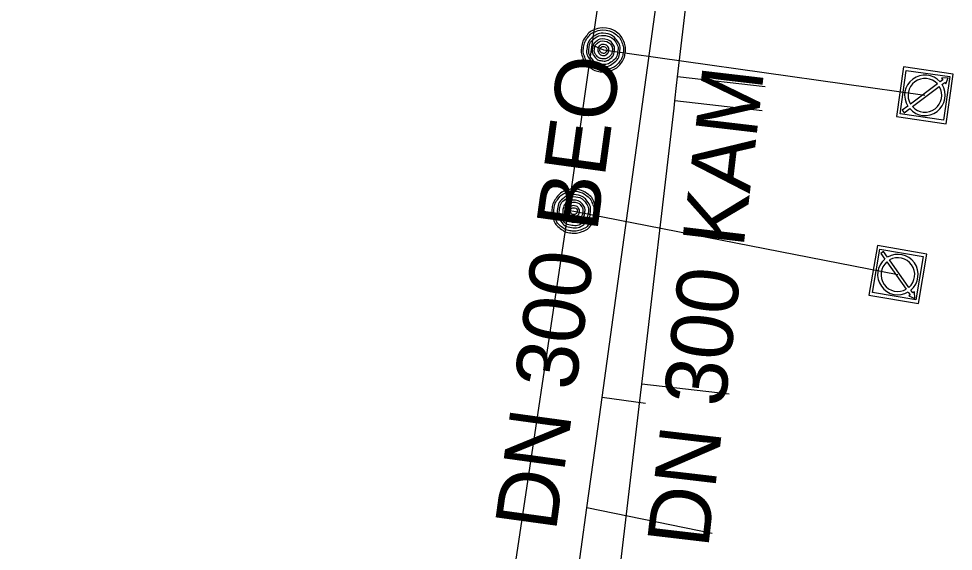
# Model space of a CAD drawing. Extents: x -595129 to -593591, y -1168385 to -1166898.
# Drawn here: x -594649.24 to -594628.01, y -1167201.97 to -1167189.88 of the extents above; entities that cross this region are included whole.
import ezdxf

# ---------------------------------------------------------------- set-up
doc = ezdxf.new("R2010")
doc.units = 0
for name, color, linetype in [('DA Kanalizační stoka popis', 7, 'Continuous'), ('Default', 7, 'Continuous'), ('Kanalizační přípojka', 7, 'Continuous'), ('Kanalizační stoka', 7, 'Continuous'), ('V Odběrné místo', 7, 'Continuous'), ('V Přípojka', 7, 'Continuous'), ('V Řad', 7, 'Continuous')]:
    doc.layers.add(name, color=color, linetype=linetype)

msp = doc.modelspace()

# ---------------------------------------------------------------- linework, layer by layer
at = {"layer": 'Default'}
for points in [[(-594635.888, -1167190.093), (-594635.764, -1167190.111), (-594635.654, -1167190.192), (-594635.545, -1167190.273), (-594635.495, -1167190.401), (-594635.445, -1167190.53), (-594635.464, -1167190.66), (-594635.482, -1167190.789), (-594635.564, -1167190.897), (-594635.646, -1167191.006), (-594635.774, -1167191.054), (-594635.901, -1167191.102), (-594636.03, -1167191.084), (-594636.159, -1167191.066), (-594636.267, -1167190.983), (-594636.376, -1167190.901), (-594636.424, -1167190.774), (-594636.473, -1167190.647), (-594636.454, -1167190.518), (-594636.436, -1167190.388), (-594636.352, -1167190.279), (-594636.269, -1167190.169), (-594636.141, -1167190.122), (-594636.014, -1167190.075), (-594635.888, -1167190.093)], [(-594635.895, -1167190.139), (-594636.008, -1167190.123), (-594636.124, -1167190.166), (-594636.24, -1167190.208), (-594636.315, -1167190.308), (-594636.391, -1167190.407), (-594636.408, -1167190.525), (-594636.425, -1167190.641), (-594636.381, -1167190.756), (-594636.337, -1167190.872), (-594636.238, -1167190.946), (-594636.14, -1167191.021), (-594636.024, -1167191.037), (-594635.907, -1167191.054), (-594635.791, -1167191.01), (-594635.675, -1167190.966), (-594635.601, -1167190.868), (-594635.527, -1167190.77), (-594635.51, -1167190.653), (-594635.493, -1167190.536), (-594635.539, -1167190.419), (-594635.584, -1167190.302), (-594635.683, -1167190.229), (-594635.782, -1167190.156), (-594635.895, -1167190.139)], [(-594635.907, -1167190.217), (-594635.75, -1167190.239), (-594635.658, -1167190.364), (-594635.565, -1167190.488), (-594635.587, -1167190.642), (-594635.609, -1167190.796), (-594635.734, -1167190.889), (-594635.858, -1167190.982), (-594636.013, -1167190.96), (-594636.166, -1167190.938), (-594636.259, -1167190.814), (-594636.353, -1167190.69), (-594636.331, -1167190.536), (-594636.308, -1167190.381), (-594636.185, -1167190.288), (-594636.062, -1167190.195), (-594635.907, -1167190.217)], [(-594635.913, -1167190.262), (-594636.049, -1167190.243), (-594636.157, -1167190.324), (-594636.266, -1167190.406), (-594636.285, -1167190.541), (-594636.304, -1167190.676), (-594636.223, -1167190.785), (-594636.142, -1167190.893), (-594636.006, -1167190.913), (-594635.871, -1167190.932), (-594635.763, -1167190.85), (-594635.654, -1167190.769), (-594635.635, -1167190.634), (-594635.615, -1167190.499), (-594635.696, -1167190.39), (-594635.777, -1167190.282), (-594635.913, -1167190.262)], [(-594635.924, -1167190.341), (-594635.82, -1167190.356), (-594635.758, -1167190.439), (-594635.697, -1167190.521), (-594635.711, -1167190.624), (-594635.726, -1167190.727), (-594635.809, -1167190.789), (-594635.892, -1167190.851), (-594635.995, -1167190.836), (-594636.097, -1167190.822), (-594636.159, -1167190.739), (-594636.221, -1167190.656), (-594636.207, -1167190.554), (-594636.192, -1167190.45), (-594636.11, -1167190.388), (-594636.027, -1167190.326), (-594635.924, -1167190.341)], [(-594635.931, -1167190.387), (-594636.014, -1167190.375), (-594636.081, -1167190.425), (-594636.149, -1167190.475), (-594636.161, -1167190.559), (-594636.173, -1167190.643), (-594636.122, -1167190.71), (-594636.072, -1167190.777), (-594635.988, -1167190.789), (-594635.905, -1167190.801), (-594635.837, -1167190.751), (-594635.77, -1167190.7), (-594635.758, -1167190.617), (-594635.746, -1167190.533), (-594635.796, -1167190.466), (-594635.847, -1167190.399), (-594635.931, -1167190.387)], [(-594635.942, -1167190.465), (-594635.889, -1167190.472), (-594635.859, -1167190.514), (-594635.828, -1167190.555), (-594635.835, -1167190.606), (-594635.842, -1167190.658), (-594635.884, -1167190.689), (-594635.925, -1167190.72), (-594635.977, -1167190.712), (-594636.028, -1167190.705), (-594636.059, -1167190.664), (-594636.09, -1167190.622), (-594636.083, -1167190.571), (-594636.075, -1167190.519), (-594636.034, -1167190.488), (-594635.993, -1167190.457), (-594635.942, -1167190.465)], [(-594635.948, -1167190.511), (-594635.98, -1167190.506), (-594636.006, -1167190.525), (-594636.032, -1167190.544), (-594636.037, -1167190.577), (-594636.041, -1167190.609), (-594636.022, -1167190.635), (-594636.002, -1167190.661), (-594635.97, -1167190.666), (-594635.938, -1167190.671), (-594635.912, -1167190.651), (-594635.887, -1167190.631), (-594635.882, -1167190.6), (-594635.877, -1167190.567), (-594635.896, -1167190.541), (-594635.915, -1167190.516), (-594635.948, -1167190.511)], [(-594636.558, -1167193.753), (-594636.434, -1167193.771), (-594636.324, -1167193.852), (-594636.215, -1167193.933), (-594636.165, -1167194.061), (-594636.115, -1167194.19), (-594636.134, -1167194.32), (-594636.152, -1167194.449), (-594636.234, -1167194.557), (-594636.316, -1167194.666), (-594636.444, -1167194.714), (-594636.571, -1167194.762), (-594636.7, -1167194.744), (-594636.829, -1167194.726), (-594636.937, -1167194.643), (-594637.046, -1167194.561), (-594637.094, -1167194.434), (-594637.143, -1167194.307), (-594637.124, -1167194.178), (-594637.106, -1167194.048), (-594637.022, -1167193.939), (-594636.939, -1167193.829), (-594636.811, -1167193.782), (-594636.684, -1167193.735), (-594636.558, -1167193.753)], [(-594636.565, -1167193.799), (-594636.678, -1167193.783), (-594636.794, -1167193.826), (-594636.91, -1167193.868), (-594636.985, -1167193.968), (-594637.061, -1167194.067), (-594637.078, -1167194.185), (-594637.095, -1167194.301), (-594637.051, -1167194.416), (-594637.007, -1167194.532), (-594636.908, -1167194.606), (-594636.81, -1167194.681), (-594636.694, -1167194.697), (-594636.577, -1167194.714), (-594636.461, -1167194.67), (-594636.345, -1167194.626), (-594636.271, -1167194.528), (-594636.197, -1167194.43), (-594636.18, -1167194.313), (-594636.163, -1167194.196), (-594636.209, -1167194.079), (-594636.254, -1167193.962), (-594636.353, -1167193.889), (-594636.452, -1167193.816), (-594636.565, -1167193.799)], [(-594636.577, -1167193.877), (-594636.42, -1167193.899), (-594636.328, -1167194.024), (-594636.235, -1167194.148), (-594636.257, -1167194.302), (-594636.279, -1167194.456), (-594636.404, -1167194.549), (-594636.528, -1167194.642), (-594636.683, -1167194.62), (-594636.836, -1167194.598), (-594636.929, -1167194.474), (-594637.023, -1167194.35), (-594637.001, -1167194.196), (-594636.978, -1167194.041), (-594636.855, -1167193.948), (-594636.732, -1167193.855), (-594636.577, -1167193.877)], [(-594636.583, -1167193.922), (-594636.719, -1167193.903), (-594636.827, -1167193.984), (-594636.936, -1167194.066), (-594636.955, -1167194.201), (-594636.974, -1167194.336), (-594636.893, -1167194.445), (-594636.812, -1167194.553), (-594636.676, -1167194.573), (-594636.541, -1167194.592), (-594636.433, -1167194.51), (-594636.324, -1167194.429), (-594636.305, -1167194.294), (-594636.285, -1167194.159), (-594636.366, -1167194.05), (-594636.447, -1167193.942), (-594636.583, -1167193.922)], [(-594636.594, -1167194.001), (-594636.49, -1167194.016), (-594636.428, -1167194.099), (-594636.367, -1167194.181), (-594636.381, -1167194.284), (-594636.396, -1167194.387), (-594636.479, -1167194.449), (-594636.562, -1167194.511), (-594636.665, -1167194.496), (-594636.767, -1167194.482), (-594636.829, -1167194.399), (-594636.891, -1167194.316), (-594636.877, -1167194.214), (-594636.862, -1167194.11), (-594636.78, -1167194.048), (-594636.697, -1167193.986), (-594636.594, -1167194.001)], [(-594636.601, -1167194.047), (-594636.684, -1167194.035), (-594636.751, -1167194.085), (-594636.819, -1167194.135), (-594636.831, -1167194.219), (-594636.843, -1167194.303), (-594636.792, -1167194.37), (-594636.742, -1167194.437), (-594636.658, -1167194.449), (-594636.575, -1167194.461), (-594636.507, -1167194.411), (-594636.44, -1167194.36), (-594636.428, -1167194.277), (-594636.416, -1167194.193), (-594636.466, -1167194.126), (-594636.517, -1167194.059), (-594636.601, -1167194.047)], [(-594636.612, -1167194.125), (-594636.559, -1167194.132), (-594636.529, -1167194.174), (-594636.498, -1167194.215), (-594636.505, -1167194.266), (-594636.512, -1167194.318), (-594636.554, -1167194.349), (-594636.595, -1167194.38), (-594636.647, -1167194.372), (-594636.698, -1167194.365), (-594636.729, -1167194.324), (-594636.76, -1167194.282), (-594636.753, -1167194.231), (-594636.745, -1167194.179), (-594636.704, -1167194.148), (-594636.663, -1167194.117), (-594636.612, -1167194.125)], [(-594636.618, -1167194.171), (-594636.65, -1167194.166), (-594636.676, -1167194.185), (-594636.702, -1167194.204), (-594636.707, -1167194.237), (-594636.711, -1167194.269), (-594636.692, -1167194.295), (-594636.672, -1167194.321), (-594636.64, -1167194.326), (-594636.608, -1167194.331), (-594636.582, -1167194.311), (-594636.557, -1167194.291), (-594636.552, -1167194.26), (-594636.547, -1167194.227), (-594636.566, -1167194.201), (-594636.585, -1167194.176), (-594636.618, -1167194.171)]]:
    msp.add_open_spline(points, degree=3, dxfattribs=at)
at = {"layer": 'Kanalizační přípojka'}
for points in [[(-594632.285, -1167191.429), (-594634.272, -1167191.198)], [(-594632.349, -1167191.974), (-594634.335, -1167191.742)], [(-594633.101, -1167198.407), (-594635.087, -1167198.175)], [(-594634.999, -1167198.617), (-594635.99, -1167198.481)], [(-594633.486, -1167201.568), (-594636.335, -1167200.987)]]:
    msp.add_lwpolyline(points, dxfattribs=at)
at = {"layer": 'Kanalizační stoka'}
for points in [[(-594636.329, -1167208.793), (-594635.893, -1167205.062), (-594635.862, -1167204.795), (-594635.117, -1167198.428), (-594635.087, -1167198.175), (-594634.355, -1167191.912), (-594634.335, -1167191.742), (-594634.295, -1167191.396), (-594634.272, -1167191.198), (-594633.905, -1167188.058), (-594633.866, -1167187.724), (-594632.763, -1167178.295), (-594632.749, -1167178.175), (-594631.455, -1167167.111)], [(-594636.851, -1167204.742), (-594636.335, -1167200.987), (-594636.148, -1167199.631), (-594635.99, -1167198.481), (-594634.793, -1167189.784), (-594633.946, -1167183.631), (-594632.742, -1167174.884), (-594632.595, -1167173.813), (-594632.407, -1167172.447), (-594631.869, -1167168.534)]]:
    msp.add_lwpolyline(points, dxfattribs=at)
at = {"layer": 'V Odběrné místo'}
for p, q in [((-594628.372, -1167191.361), (-594628.983, -1167191.819)), ((-594628.94, -1167191.876), (-594628.329, -1167191.419)), ((-594629.519, -1167195.399), (-594629.079, -1167196.022)), ((-594629.02, -1167195.981), (-594629.461, -1167195.358))]:
    msp.add_line(p, q, dxfattribs=at)
for points in [[(-594629.301, -1167192.102), (-594628.173, -1167192.264), (-594628.011, -1167191.136), (-594629.139, -1167190.974)], [(-594629.22, -1167192.042), (-594629.079, -1167191.055), (-594628.092, -1167191.196), (-594628.233, -1167192.183)], [(-594629.736, -1167195.032), (-594629.928, -1167196.156), (-594628.804, -1167196.348), (-594628.612, -1167195.224)], [(-594629.678, -1167195.114), (-594628.694, -1167195.282), (-594628.862, -1167196.266), (-594629.846, -1167196.098)]]:
    msp.add_lwpolyline(points, close=True, dxfattribs=at)
for points in [[(-594628.268, -1167191.372), (-594628.206, -1167191.326), (-594628.182, -1167191.359), (-594628.127, -1167191.22), (-594628.277, -1167191.232), (-594628.249, -1167191.269), (-594628.311, -1167191.316)], [(-594629.044, -1167191.865), (-594629.169, -1167191.959), (-594629.127, -1167192.016), (-594629.002, -1167191.922)], [(-594629.505, -1167195.295), (-594629.596, -1167195.168), (-594629.654, -1167195.209), (-594629.564, -1167195.336)], [(-594629.034, -1167196.085), (-594628.989, -1167196.148), (-594629.023, -1167196.171), (-594628.885, -1167196.229), (-594628.894, -1167196.08), (-594628.931, -1167196.107), (-594628.976, -1167196.043)]]:
    msp.add_lwpolyline(points, dxfattribs=at)
for centre, radius, start, end in [((-594628.656, -1167191.619), 0.46, 41.3264, 212.3806), ((-594628.656, -1167191.619), 0.383, 42.2171, 211.4899), ((-594628.656, -1167191.619), 0.46, 221.2757, 32.4309), ((-594628.656, -1167191.619), 0.383, 222.1664, 31.4869), ((-594629.27, -1167195.69), 0.46, 129.7171, 300.8722), ((-594629.27, -1167195.69), 0.46, 309.7677, 120.8219), ((-594629.27, -1167195.69), 0.383, 310.6585, 119.9312), ((-594629.27, -1167195.69), 0.383, 130.6078, 299.9283)]:
    msp.add_arc(centre, radius, start, end, dxfattribs=at)
at = {"layer": 'V Přípojka'}
for points in [[(-594636.22, -1167190.47), (-594635.96, -1167190.59), (-594628.656, -1167191.619)], [(-594636.76, -1167194.23), (-594636.629, -1167194.249), (-594629.27, -1167195.69)]]:
    msp.add_lwpolyline(points, dxfattribs=at)
at = {"layer": 'V Řad'}
msp.add_lwpolyline([(-594631.989, -1167162.976), (-594632.14, -1167163.45), (-594634.46, -1167178.7), (-594634.51, -1167179.01), (-594636.22, -1167190.47), (-594636.76, -1167194.23), (-594638.02, -1167202.66), (-594638.58, -1167206.43), (-594639.95, -1167215.78), (-594639.99, -1167216.06), (-594640.44, -1167219.03), (-594641.11, -1167223.74), (-594641.81, -1167228.64), (-594642.2, -1167231.6), (-594643.64, -1167241.59), (-594643.86, -1167243.13), (-594644.462, -1167244.928), (-594645.343, -1167251.066), (-594645.881, -1167254.818), (-594646.018, -1167255.769), (-594647.761, -1167267.914), (-594647.845, -1167268.502), (-594648.571, -1167273.559), (-594649.24, -1167278.41)], dxfattribs=at)

# ---------------------------------------------------------------- texts
at = {"layer": 'DA Kanalizační stoka popis'}
for s, rotation, p in [('DN 300 BEO', 82.1621, (-594637.04, -1167201.544)), ('DN 300 KAM', 83.3081, (-594633.58, -1167201.921))]:
    msp.add_text(s, height=1.4, rotation=rotation, dxfattribs=at).set_placement(p)

doc.saveas('drawing.dxf')
